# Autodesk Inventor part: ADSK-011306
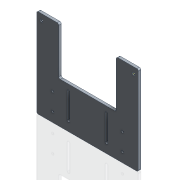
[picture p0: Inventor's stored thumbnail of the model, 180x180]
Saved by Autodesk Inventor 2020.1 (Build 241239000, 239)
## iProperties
Created: 1999-11
Part Number: ADSK-011306
Material: Pearson Aluminium
Document SubType Name: Modeling
Designer: sspink
Density: 2.71 g/cm^3
Appearance: Pearson-Aluminum
Mass: 2639.1 g
Surface Area: 2205.07 cm^2
Volume: 973.836 cm^3
Control State: 0
Checked Out: False
Last Check In By: sspink
Last Check In Date: 1999-12-16
Master: False
Shininess: 35.0
Length Units: 11269
Angle Units: 11279
Time Units: 11290
Mass Units: 11283
Length Display Precision: 3
Angle Display Precision: 2
Compacted: True
Cutlength: 14.00 X 16.00 (224 SI)
Material Desc: SHEET,ALUM,0.375
Material_number: A101290
Dimensions: 406x355x10 mm
Mass: 2,639 kg
DocNumber: ADSK-011306.ipt
Folder: 01 - Themengebiete\Simplification\01 - Packaging machine\
VDS_Category: 3D Komponenten
Density: 2.7099999999999995
Volumn: 925.3063166935369
Area: 2199.8355955673605
PropertySet Name: Model Information
Author: sspink
Revision Number: -
Title: base plate
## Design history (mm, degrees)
node "Solide1"
  node "Extrusion1" dims "d4" = 10, "d5" = 0
  node "Fillet1" dims "d6" = 6
  node "Hole1" dims "d7" = 9, "d8" = 19, "d9" = 6.35, "d10" = 90 deg, "d11" = 19.05, "d12" = 118 deg, "d59" = 6
  node "Hole2" dims "d31" = 11, "d32" = 23.5, "d33" = 6.35, "d34" = 90 deg, "d35" = 19.05, "d36" = 118 deg, "d60" = 6
  node "Extrusion2" dims "d46" = 25.4, "d47" = 0
sketch "Sketch1"
  geometry: L1 (203, 177.5)-(203, -177.5); L2 (203, -177.5)-(-203, -177.5); L3 (-203, -177.5)-(-203, 177.5); L4 (-203, 177.5)-(-115, 177.5); L5 (-115, 177.5)-(-115, -12.5); L6 (-115, -12.5)-(115, -12.5); L7 (115, -12.5)-(115, 177.5); L8 (115, 177.5)-(203, 177.5); 3 further points
  constraints: 16 end point, 6 parallel, 2 equal length, 2 midpoint, 1 horizontal alignment, 1 perpendicular, 1 vertical, 1 vertical alignment
  dimensions: "d0" = 355 distance of L1.start L1.end; "d1" = 406 distance of L1.end L2.end; "d2" = 190 distance of L6.end L7.end; "d3" = 230 distance of L5.end L6.end
workaxis "Arbeitsachse1"
workplane "Arbeitsebene5"
sketch "Sketch2"
  geometry: L1 (197, -177.5)-(-197, -177.5) reference; L2 (-177.5, -69.5)-(-139.5, -69.5); L3 (-139.5, -69.5)-(-139.5, -139.5); L4 (-139.5, -139.5)-(-177.5, -139.5); L5 (-177.5, -139.5)-(-177.5, -69.5); L6 (-109, -12.5)-(109, -12.5) reference; L7 (0, -12.5)-(0, -177.5); L8 (139.5, -69.5)-(177.5, -69.5); L9 (177.5, -69.5)-(177.5, -139.5); L10 (177.5, -139.5)-(139.5, -139.5); L11 (139.5, -139.5)-(139.5, -69.5); 4 further points
  constraints: 18 end point, 4 coincident, 4 parallel, 2 horizontal, 2 midpoint, 2 perpendicular
  dimensions: "d51" = 38 distance of L2.start L2.end; "d52" = 70 distance of L2.end L3.end; "d53" = 38 distance between parallel lines of L1 L4; "d54" = 139.5 distance between parallel lines of L7 L3; "d55" = 38 distance of L8.start L8.end (= d51); "d56" = 139.5 distance between parallel lines of L7 L11 (= d54); "d57" = 70 distance of L8.end L9.end (= d52); "d58" = 38 distance between parallel lines of L1 L10 (= d53)
sketch "Sketch4"
  geometry: L1 (-197, 177.5)-(-121, 177.5) reference; L2 (-203, -171.5)-(-203, 171.5) reference; L3 (203, 171.5)-(203, -171.5) reference; 2 further points
  constraints: 1 horizontal alignment
  dimensions: "d48" = 19 distance from line of point (-184, 152.5) L2; "d49" = 19 distance from line of point (184, 152.5) L3 (= d48); "d50" = 25 distance from line of point (-184, 152.5) L1
sketch "Sketch5"
  geometry: L1 (-203, -171.5)-(-203, 171.5) reference; L2 (197, -177.5)-(-197, -177.5) reference; L3 (-81, -37.8)-(-81, -139.5); L4 (-71, -139.5)-(-71, -37.8); L5 (71, -139.5)-(71, -37.8); L6 (81, -37.8)-(81, -139.5); L7 (-76, -37.8)-(-76, -139.5); L8 (76, -37.8)-(76, -139.5); L9 (-76, -88.65)-(76, -88.65); A1 r 5 centre (-76, -139.5) between (-81, -139.5) and (-71, -139.5); A2 r 5 centre (-76, -37.8) between (-71, -37.8) and (-81, -37.8); A3 r 5 centre (76, -139.5) between (71, -139.5) and (81, -139.5); A4 r 5 centre (76, -37.8) between (81, -37.8) and (71, -37.8); 2 further points
  constraints: 14 end point, 8 parallel, 8 point on circle, 5 tangent, 4 centre point, 4 midpoint, 1 equal radius, 1 horizontal, 1 horizontal alignment, 1 vertical alignment
  dimensions: "d38" = 5 radius of A2; "d40" = 38 distance from line of L7.end L2; "d41" = 139.7 distance from line of L2 L7.start; "d44" = 5 radius of A4 (= d38); "d61" = 152 distance of L9.start L9.end
workplane "Work Plane1"
workplane "Work Plane2"
node "Corps solides"
node "Corps surfaciques"
other parameters: "d62" = 90 deg
